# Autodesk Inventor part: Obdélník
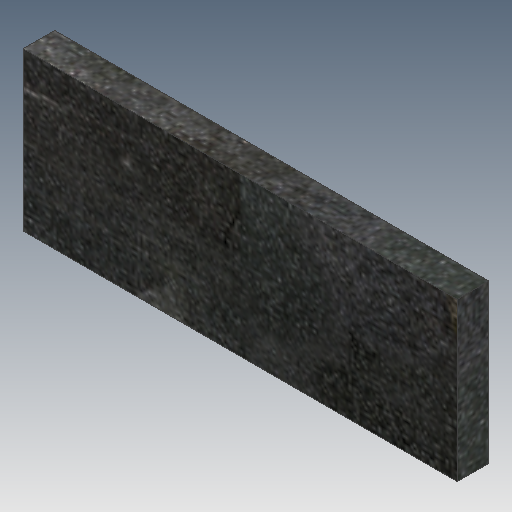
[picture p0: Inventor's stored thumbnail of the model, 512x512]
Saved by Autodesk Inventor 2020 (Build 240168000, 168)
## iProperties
Created: 2025-03
Part Number: Obdélník
Material: Ocel
Document SubType Name: Modeling
Designer: doma
Density: 7.85 g/cm^3
Appearance: Plech
Mass: 276.32 g
Surface Area: 112 cm^2
Volume: 35.2 cm^3
Author: doma
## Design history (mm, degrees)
sketch "Náčrt1"
  geometry: L1 (0, 0)-(110, 0); L2 (110, 0)-(110, 40); L3 (110, 40)-(0, 40); L4 (0, 40)-(0, 0)
  constraints: 8 end point, 2 parallel, 1 horizontal, 1 perpendicular
  dimensions: "d0" = 110 distance of L3.end L2.end; "d1" = 40 distance of L2.end L1.end
extrude "Vysunutí1" new body sketch "Náčrt1" distance "d2" = 8; taper "d3" = 0 deg
node "Těleso1"
